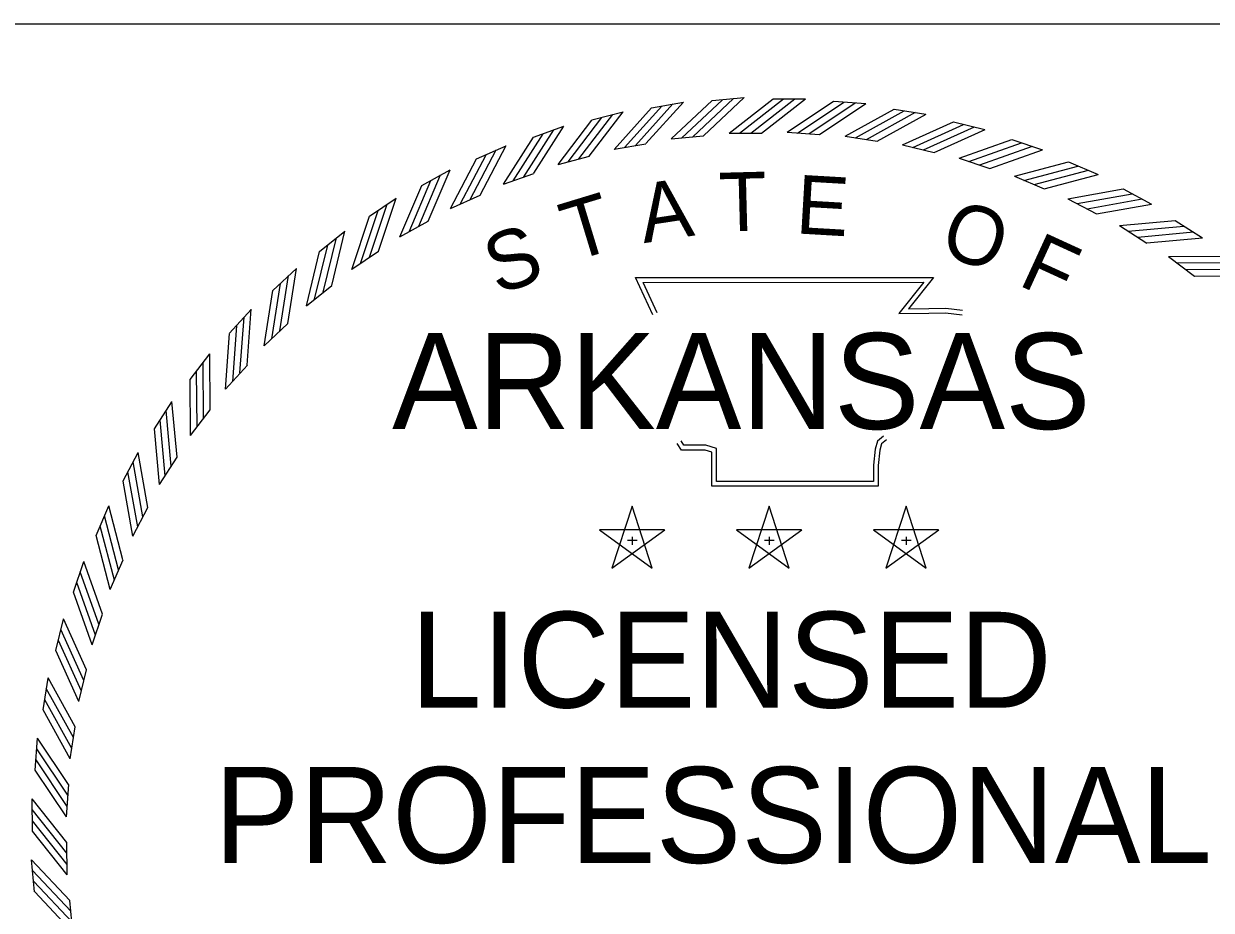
# Model space of a CAD drawing. Extents: x 0 to 1228740, y 0 to 152440.
# Drawn here: x 30.801 to 32.801, y 18.649 to 20.143 of the extents above; entities that cross this region are included whole.
import ezdxf

# ---------------------------------------------------------------- set-up
doc = ezdxf.new("R2010")
doc.units = 0
for name, color, linetype in [('R_Border', 7, 'Continuous'), ('STAMP_BOL', 7, 'Continuous'), ('STAMP_PP', 7, 'Continuous')]:
    doc.layers.add(name, color=color, linetype=linetype)

msp = doc.modelspace()

# ---------------------------------------------------------------- linework, layer by layer
at = {"layer": 'R_Border'}
msp.add_line((29.1131, 20.1432), (33.4231, 20.1432), dxfattribs=at)
at = {"layer": 'STAMP_BOL'}
for p, q in [((31.8584, 20.0015), (31.912, 20.0109)), ((31.9602, 20.0137), (32.0144, 20.0186)), ((32.0633, 20.0167), (32.1177, 20.0167)), ((32.1652, 20.0126), (32.2194, 20.0086)), ((31.7579, 19.981), (31.8105, 19.9948)), ((32.2669, 19.9994), (32.3206, 19.9909)), ((31.6595, 19.9522), (31.7108, 19.9703)), ((32.3671, 19.9778), (32.42, 19.965)), ((31.8916, 19.9492), (31.9459, 19.9542)), ((31.989, 19.9588), (32.0435, 19.9588)), ((32.0869, 19.9603), (32.1413, 19.9563)), ((32.1845, 19.9538), (32.2384, 19.9453)), ((32.4653, 19.9481), (32.5169, 19.9309)), ((31.5637, 19.9154), (31.6134, 19.9377)), ((31.7953, 19.9316), (31.849, 19.941)), ((32.2813, 19.9392), (32.3343, 19.9263)), ((31.7008, 19.9061), (31.7536, 19.9199)), ((32.3766, 19.9166), (32.4283, 19.8994)), ((32.5606, 19.9103), (32.6107, 19.8889)), ((31.4714, 19.8708), (31.519, 19.8972)), ((31.6088, 19.8729), (31.6602, 19.891)), ((32.4696, 19.8863), (32.5198, 19.8648)), ((32.6526, 19.8648), (32.7006, 19.8393)), ((31.383, 19.8188), (31.4283, 19.849)), ((31.5198, 19.8321), (31.5695, 19.8545)), ((32.5598, 19.8484), (32.608, 19.8229)), ((31.4344, 19.7842), (31.4821, 19.8106)), ((32.6466, 19.8031), (32.6926, 19.7737)), ((32.7404, 19.8119), (32.7862, 19.7825)), ((31.2992, 19.7596), (31.3419, 19.7934)), ((31.3533, 19.7294), (31.3987, 19.7597)), ((32.7294, 19.7509), (32.7727, 19.7178)), ((31.2206, 19.6937), (31.2603, 19.7309)), ((31.277, 19.6681), (31.3198, 19.702)), ((31.1477, 19.6216), (31.1842, 19.6619)), ((31.2061, 19.6007), (31.2459, 19.638)), ((31.0811, 19.5437), (31.1141, 19.5869)), ((31.1409, 19.5277), (31.1775, 19.5681)), ((31.021, 19.4605), (31.0504, 19.5063)), ((31.082, 19.4495), (31.1151, 19.4928)), ((30.9681, 19.3727), (30.9935, 19.4207)), ((31.0298, 19.3667), (31.0592, 19.4127)), ((30.9226, 19.2807), (30.944, 19.3308)), ((30.9845, 19.28), (31.01, 19.3281)), ((31.8255, 19.3302), (31.7915, 19.2258)), ((31.8594, 19.2258), (31.8256, 19.3303)), ((32.0563, 19.3302), (32.0222, 19.2258)), ((32.0902, 19.2258), (32.0564, 19.3303)), ((32.2871, 19.3302), (32.253, 19.2258)), ((32.321, 19.2258), (32.2871, 19.3303)), ((31.8804, 19.2904), (31.7705, 19.2905)), ((31.7706, 19.2904), (31.8594, 19.2257)), ((31.7916, 19.2258), (31.8805, 19.2903)), ((32.1112, 19.2904), (32.0013, 19.2905)), ((32.0014, 19.2904), (32.0902, 19.2257)), ((32.0224, 19.2258), (32.1113, 19.2903)), ((32.3419, 19.2904), (32.2321, 19.2905)), ((32.2322, 19.2904), (32.321, 19.2257)), ((32.2532, 19.2258), (32.3421, 19.2903)), ((31.8177, 19.2728), (31.834, 19.2728)), ((31.8256, 19.2787), (31.8256, 19.2649)), ((32.0485, 19.2728), (32.0648, 19.2728)), ((32.0564, 19.2787), (32.0564, 19.2649)), ((32.2793, 19.2728), (32.2956, 19.2728)), ((32.2872, 19.2787), (32.2872, 19.2649)), ((30.8848, 19.1854), (30.902, 19.237)), ((30.9466, 19.1897), (30.9681, 19.2399)), ((30.9163, 19.0967), (30.9335, 19.1484)), ((30.855, 19.0873), (30.8679, 19.1401)), ((30.8937, 19.0014), (30.9066, 19.0544)), ((30.8335, 18.987), (30.8419, 19.0407)), ((30.8791, 18.9046), (30.8876, 18.9585)), ((30.8203, 18.8853), (30.8243, 18.9395)), ((30.8726, 18.807), (30.8766, 18.8614)), ((30.8155, 18.7828), (30.815, 18.8372)), ((30.8741, 18.7091), (30.8736, 18.7637)), ((30.8192, 18.6803), (30.8142, 18.7345)), ((30.8837, 18.6117), (30.8787, 18.666))]:
    msp.add_line(p, q, dxfattribs=at)
for points in [[(31.8126, 19.9344), (31.8756, 20.0043)], [(31.8311, 19.9381), (31.8941, 20.008)], [(31.849, 19.9411), (31.912, 20.011)], [(31.8916, 19.9491), (31.9602, 20.0136)], [(31.909, 19.9506), (31.9776, 20.015)], [(31.9278, 19.9527), (31.9964, 20.0172)], [(31.9458, 19.9542), (32.0145, 20.0187)], [(31.9889, 19.9587), (32.0632, 20.0166)], [(32.0065, 19.9586), (32.0807, 20.0165)], [(32.0254, 19.959), (32.0996, 20.0169)], [(32.0435, 19.9588), (32.1177, 20.0167)], [(32.0868, 19.9603), (32.1651, 20.0126)], [(32.1043, 19.9588), (32.1825, 20.0111)], [(32.1231, 19.9579), (32.2014, 20.0101)], [(32.1412, 19.9564), (32.2195, 20.0087)], [(31.7178, 19.9103), (31.7748, 19.9852)], [(31.7359, 19.9155), (31.793, 19.9904)], [(31.7535, 19.92), (31.8106, 19.9948)], [(31.7953, 19.9315), (31.8583, 20.0014)], [(32.1845, 19.9537), (32.2668, 19.9994)], [(32.2017, 19.9508), (32.2841, 19.9965)], [(32.2205, 19.9483), (32.3028, 19.994)], [(32.2383, 19.9453), (32.3207, 19.991)], [(31.643, 19.8852), (31.6937, 19.9645)], [(31.6601, 19.8911), (31.7108, 19.9704)], [(31.7008, 19.906), (31.7579, 19.9809)], [(32.2812, 19.9391), (32.3671, 19.9778)], [(32.2982, 19.9348), (32.384, 19.9735)], [(32.3167, 19.9308), (32.4025, 19.9695)], [(32.3342, 19.9263), (32.4201, 19.965)], [(31.6087, 19.8728), (31.6594, 19.9521)], [(31.6253, 19.8785), (31.676, 19.9578)], [(32.3765, 19.9166), (32.4652, 19.9481)], [(31.5528, 19.8472), (31.5968, 19.9305)], [(31.5694, 19.8545), (31.6134, 19.9378)], [(32.393, 19.9109), (32.4818, 19.9424)], [(32.4111, 19.9053), (32.4998, 19.9368)], [(32.4282, 19.8994), (32.517, 19.9309)], [(31.5197, 19.8321), (31.5637, 19.9153)], [(31.5358, 19.8391), (31.5797, 19.9224)], [(32.4695, 19.8863), (32.5606, 19.9103)], [(32.4856, 19.8792), (32.5766, 19.9033)], [(31.4661, 19.802), (31.5031, 19.8886)], [(31.4821, 19.8106), (31.519, 19.8972)], [(32.5031, 19.8722), (32.5941, 19.8962)], [(32.5197, 19.8649), (32.6107, 19.8889)], [(31.4344, 19.7842), (31.4713, 19.8707)], [(31.4498, 19.7925), (31.4867, 19.8791)], [(32.5598, 19.8483), (32.6525, 19.8648)], [(31.3986, 19.7597), (31.4283, 19.849)], [(32.5752, 19.84), (32.6679, 19.8565)], [(32.5921, 19.8315), (32.6848, 19.848)], [(31.368, 19.7389), (31.3976, 19.8283)], [(31.3835, 19.7498), (31.4131, 19.8391)], [(32.608, 19.8229), (32.7007, 19.8394)], [(31.3533, 19.7293), (31.383, 19.8187)], [(32.6466, 19.8031), (32.7403, 19.8119)], [(31.3197, 19.702), (31.3419, 19.7935)], [(32.6612, 19.7935), (32.755, 19.8023)], [(32.6774, 19.7837), (32.7711, 19.7924)], [(31.2908, 19.6788), (31.313, 19.7703)], [(31.3054, 19.6909), (31.3276, 19.7823)], [(32.6925, 19.7738), (32.7863, 19.7825)], [(31.277, 19.668), (31.2992, 19.7595)], [(32.7293, 19.7509), (32.8235, 19.7518)], [(31.2458, 19.638), (31.2603, 19.731)], [(32.7431, 19.7401), (32.8373, 19.7411)], [(32.7584, 19.729), (32.8526, 19.7299)], [(31.2189, 19.6125), (31.2335, 19.7055)], [(31.2324, 19.6257), (31.247, 19.7187)], [(31.8606, 19.6525), (31.8316, 19.7154), (32.3333, 19.7156), (32.2914, 19.663), (32.3255, 19.6634), (32.354, 19.6638), (32.3824, 19.6607)], [(31.8678, 19.6559), (31.844, 19.7074), (32.3169, 19.7077), (32.2748, 19.6548), (32.3256, 19.6555), (32.3536, 19.6558), (32.3816, 19.6528)], [(32.7727, 19.7179), (32.8669, 19.7188)], [(31.2061, 19.6006), (31.2206, 19.6936)], [(31.1651, 19.5548), (31.172, 19.6487)], [(31.1774, 19.5681), (31.1842, 19.662)], [(31.1528, 19.5405), (31.1596, 19.6344)], [(31.1409, 19.5276), (31.1477, 19.6215)], [(31.115, 19.4928), (31.1141, 19.587)], [(31.1039, 19.4785), (31.1029, 19.5727)], [(31.082, 19.4494), (31.0811, 19.5436)], [(31.0928, 19.4632), (31.0918, 19.5574)], [(31.0591, 19.4126), (31.0504, 19.5064)], [(31.0492, 19.3975), (31.0405, 19.4912)], [(31.0393, 19.3813), (31.0306, 19.4751)], [(31.0298, 19.3667), (31.021, 19.4604)], [(32.2493, 19.4484), (32.2387, 19.4399), (32.235, 19.4264), (32.2321, 19.3993), (32.2321, 19.3721), (31.9679, 19.3721), (31.9679, 19.411), (31.9679, 19.4273), (31.9497, 19.4328), (31.913, 19.4328), (31.9083, 19.4401)], [(32.2543, 19.4423), (32.2457, 19.4353), (32.2429, 19.4249), (32.24, 19.3989), (32.24, 19.3642), (31.9599, 19.3642), (31.9599, 19.411), (31.9599, 19.4214), (31.9486, 19.4249), (31.9087, 19.4249), (31.9016, 19.4357)], [(31.0013, 19.3122), (30.9849, 19.4049)], [(31.01, 19.3281), (30.9935, 19.4208)], [(30.9929, 19.2953), (30.9764, 19.388)], [(30.9845, 19.2799), (30.9681, 19.3726)], [(30.968, 19.2398), (30.944, 19.3308)], [(30.9607, 19.2232), (30.9367, 19.3142)], [(30.9537, 19.2057), (30.9296, 19.2967)], [(30.9466, 19.1896), (30.9226, 19.2807)], [(30.9335, 19.1484), (30.902, 19.2371)], [(30.9276, 19.1312), (30.8961, 19.2199)], [(30.9163, 19.0966), (30.8848, 19.1853)], [(30.922, 19.1131), (30.8905, 19.2019)], [(30.9066, 19.0544), (30.8679, 19.1402)], [(30.8981, 19.0183), (30.8594, 19.1041)], [(30.9021, 19.0368), (30.8634, 19.1226)], [(30.8938, 19.0013), (30.8551, 19.0872)], [(30.8846, 18.9406), (30.8389, 19.0229)], [(30.8876, 18.9585), (30.8419, 19.0408)], [(30.8821, 18.9218), (30.8364, 19.0042)], [(30.8792, 18.9046), (30.8335, 18.9869)], [(30.8765, 18.8613), (30.8242, 18.9396)], [(30.875, 18.8432), (30.8227, 18.9215)], [(30.8726, 18.8069), (30.8203, 18.8852)], [(30.8741, 18.8244), (30.8218, 18.9026)], [(30.8736, 18.7636), (30.815, 18.8373)], [(30.8736, 18.7455), (30.815, 18.8192)], [(30.8741, 18.7266), (30.8156, 18.8003)], [(30.8741, 18.7091), (30.8156, 18.7828)], [(30.8787, 18.666), (30.8142, 18.7346)], [(30.8802, 18.6479), (30.8157, 18.7165)], [(30.8823, 18.6291), (30.8178, 18.6977)], [(30.8838, 18.6117), (30.8193, 18.6803)]]:
    msp.add_lwpolyline(points, dxfattribs=at)
at = {"layer": 'STAMP_PP'}
for p, q in [((31.8584, 20.0015), (31.912, 20.0109)), ((31.9602, 20.0137), (32.0144, 20.0186)), ((32.0633, 20.0167), (32.1177, 20.0167)), ((32.1652, 20.0126), (32.2194, 20.0086)), ((31.7579, 19.981), (31.8105, 19.9948)), ((32.2669, 19.9994), (32.3206, 19.9909)), ((31.6595, 19.9522), (31.7108, 19.9703)), ((32.3671, 19.9778), (32.42, 19.965)), ((31.8916, 19.9492), (31.9459, 19.9542)), ((31.989, 19.9588), (32.0435, 19.9588)), ((32.0869, 19.9603), (32.1413, 19.9563)), ((32.1845, 19.9538), (32.2384, 19.9453)), ((32.4653, 19.9481), (32.5169, 19.9309)), ((31.5637, 19.9154), (31.6134, 19.9377)), ((31.7953, 19.9316), (31.849, 19.941)), ((32.2813, 19.9392), (32.3343, 19.9263)), ((31.7008, 19.9061), (31.7536, 19.9199)), ((32.3766, 19.9166), (32.4283, 19.8994)), ((32.5606, 19.9103), (32.6107, 19.8889)), ((31.4714, 19.8708), (31.519, 19.8972)), ((31.6088, 19.8729), (31.6602, 19.891)), ((32.4696, 19.8863), (32.5198, 19.8648)), ((32.6526, 19.8648), (32.7006, 19.8393)), ((31.383, 19.8188), (31.4283, 19.849)), ((31.5198, 19.8321), (31.5695, 19.8545)), ((32.5598, 19.8484), (32.608, 19.8229)), ((31.4344, 19.7842), (31.4821, 19.8106)), ((32.6466, 19.8031), (32.6926, 19.7737)), ((32.7404, 19.8119), (32.7862, 19.7825)), ((31.2992, 19.7596), (31.3419, 19.7934)), ((31.3533, 19.7294), (31.3987, 19.7597)), ((32.7294, 19.7509), (32.7727, 19.7178)), ((31.2206, 19.6937), (31.2603, 19.7309)), ((31.277, 19.6681), (31.3198, 19.702)), ((31.1477, 19.6216), (31.1842, 19.6619)), ((31.2061, 19.6007), (31.2459, 19.638)), ((31.0811, 19.5437), (31.1141, 19.5869)), ((31.1409, 19.5277), (31.1775, 19.5681)), ((31.021, 19.4605), (31.0504, 19.5063)), ((31.082, 19.4495), (31.1151, 19.4928)), ((30.9681, 19.3727), (30.9935, 19.4207)), ((31.0298, 19.3667), (31.0592, 19.4127)), ((30.9226, 19.2807), (30.944, 19.3308)), ((30.9845, 19.28), (31.01, 19.3281)), ((31.8255, 19.3302), (31.7915, 19.2258)), ((31.8594, 19.2258), (31.8256, 19.3303)), ((32.0563, 19.3302), (32.0222, 19.2258)), ((32.0902, 19.2258), (32.0564, 19.3303)), ((32.2871, 19.3302), (32.253, 19.2258)), ((32.321, 19.2258), (32.2871, 19.3303)), ((31.8804, 19.2904), (31.7705, 19.2905)), ((31.7706, 19.2904), (31.8594, 19.2257)), ((31.7916, 19.2258), (31.8805, 19.2903)), ((32.1112, 19.2904), (32.0013, 19.2905)), ((32.0014, 19.2904), (32.0902, 19.2257)), ((32.0224, 19.2258), (32.1113, 19.2903)), ((32.3419, 19.2904), (32.2321, 19.2905)), ((32.2322, 19.2904), (32.321, 19.2257)), ((32.2532, 19.2258), (32.3421, 19.2903)), ((31.8177, 19.2728), (31.834, 19.2728)), ((31.8256, 19.2787), (31.8256, 19.2649)), ((32.0485, 19.2728), (32.0648, 19.2728)), ((32.0564, 19.2787), (32.0564, 19.2649)), ((32.2793, 19.2728), (32.2956, 19.2728)), ((32.2872, 19.2787), (32.2872, 19.2649)), ((30.8848, 19.1854), (30.902, 19.237)), ((30.9466, 19.1897), (30.9681, 19.2399)), ((30.9163, 19.0967), (30.9335, 19.1484)), ((30.855, 19.0873), (30.8679, 19.1401)), ((30.8937, 19.0014), (30.9066, 19.0544)), ((30.8335, 18.987), (30.8419, 19.0407)), ((30.8791, 18.9046), (30.8876, 18.9585)), ((30.8203, 18.8853), (30.8243, 18.9395)), ((30.8726, 18.807), (30.8766, 18.8614)), ((30.8155, 18.7828), (30.815, 18.8372)), ((30.8741, 18.7091), (30.8736, 18.7637)), ((30.8192, 18.6803), (30.8142, 18.7345)), ((30.8837, 18.6117), (30.8787, 18.666))]:
    msp.add_line(p, q, dxfattribs=at)
for points in [[(31.8126, 19.9344), (31.8756, 20.0043)], [(31.8311, 19.9381), (31.8941, 20.008)], [(31.849, 19.9411), (31.912, 20.011)], [(31.8916, 19.9491), (31.9602, 20.0136)], [(31.909, 19.9506), (31.9776, 20.015)], [(31.9278, 19.9527), (31.9964, 20.0172)], [(31.9458, 19.9542), (32.0145, 20.0187)], [(31.9889, 19.9587), (32.0632, 20.0166)], [(32.0065, 19.9586), (32.0807, 20.0165)], [(32.0254, 19.959), (32.0996, 20.0169)], [(32.0435, 19.9588), (32.1177, 20.0167)], [(32.0868, 19.9603), (32.1651, 20.0126)], [(32.1043, 19.9588), (32.1825, 20.0111)], [(32.1231, 19.9579), (32.2014, 20.0101)], [(32.1412, 19.9564), (32.2195, 20.0087)], [(31.7178, 19.9103), (31.7748, 19.9852)], [(31.7359, 19.9155), (31.793, 19.9904)], [(31.7535, 19.92), (31.8106, 19.9948)], [(31.7953, 19.9315), (31.8583, 20.0014)], [(32.1845, 19.9537), (32.2668, 19.9994)], [(32.2017, 19.9508), (32.2841, 19.9965)], [(32.2205, 19.9483), (32.3028, 19.994)], [(32.2383, 19.9453), (32.3207, 19.991)], [(31.643, 19.8852), (31.6937, 19.9645)], [(31.6601, 19.8911), (31.7108, 19.9704)], [(31.7008, 19.906), (31.7579, 19.9809)], [(32.2812, 19.9391), (32.3671, 19.9778)], [(32.2982, 19.9348), (32.384, 19.9735)], [(32.3167, 19.9308), (32.4025, 19.9695)], [(32.3342, 19.9263), (32.4201, 19.965)], [(31.6087, 19.8728), (31.6594, 19.9521)], [(31.6253, 19.8785), (31.676, 19.9578)], [(32.3765, 19.9166), (32.4652, 19.9481)], [(31.5528, 19.8472), (31.5968, 19.9305)], [(31.5694, 19.8545), (31.6134, 19.9378)], [(32.393, 19.9109), (32.4818, 19.9424)], [(32.4111, 19.9053), (32.4998, 19.9368)], [(32.4282, 19.8994), (32.517, 19.9309)], [(31.5197, 19.8321), (31.5637, 19.9153)], [(31.5358, 19.8391), (31.5797, 19.9224)], [(32.4695, 19.8863), (32.5606, 19.9103)], [(32.4856, 19.8792), (32.5766, 19.9033)], [(31.4661, 19.802), (31.5031, 19.8886)], [(31.4821, 19.8106), (31.519, 19.8972)], [(32.5031, 19.8722), (32.5941, 19.8962)], [(32.5197, 19.8649), (32.6107, 19.8889)], [(31.4344, 19.7842), (31.4713, 19.8707)], [(31.4498, 19.7925), (31.4867, 19.8791)], [(32.5598, 19.8483), (32.6525, 19.8648)], [(31.3986, 19.7597), (31.4283, 19.849)], [(32.5752, 19.84), (32.6679, 19.8565)], [(32.5921, 19.8315), (32.6848, 19.848)], [(31.368, 19.7389), (31.3976, 19.8283)], [(31.3835, 19.7498), (31.4131, 19.8391)], [(32.608, 19.8229), (32.7007, 19.8394)], [(31.3533, 19.7293), (31.383, 19.8187)], [(32.6466, 19.8031), (32.7403, 19.8119)], [(31.3197, 19.702), (31.3419, 19.7935)], [(32.6612, 19.7935), (32.755, 19.8023)], [(32.6774, 19.7837), (32.7711, 19.7924)], [(31.2908, 19.6788), (31.313, 19.7703)], [(31.3054, 19.6909), (31.3276, 19.7823)], [(32.6925, 19.7738), (32.7863, 19.7825)], [(31.277, 19.668), (31.2992, 19.7595)], [(32.7293, 19.7509), (32.8235, 19.7518)], [(31.2458, 19.638), (31.2603, 19.731)], [(32.7431, 19.7401), (32.8373, 19.7411)], [(32.7584, 19.729), (32.8526, 19.7299)], [(31.2189, 19.6125), (31.2335, 19.7055)], [(31.2324, 19.6257), (31.247, 19.7187)], [(31.8606, 19.6525), (31.8316, 19.7154), (32.3333, 19.7156), (32.2914, 19.663), (32.3255, 19.6634), (32.354, 19.6638), (32.3824, 19.6607)], [(31.8678, 19.6559), (31.844, 19.7074), (32.3169, 19.7077), (32.2748, 19.6548), (32.3256, 19.6555), (32.3536, 19.6558), (32.3816, 19.6528)], [(32.7727, 19.7179), (32.8669, 19.7188)], [(31.2061, 19.6006), (31.2206, 19.6936)], [(31.1651, 19.5548), (31.172, 19.6487)], [(31.1774, 19.5681), (31.1842, 19.662)], [(31.1528, 19.5405), (31.1596, 19.6344)], [(31.1409, 19.5276), (31.1477, 19.6215)], [(31.115, 19.4928), (31.1141, 19.587)], [(31.1039, 19.4785), (31.1029, 19.5727)], [(31.082, 19.4494), (31.0811, 19.5436)], [(31.0928, 19.4632), (31.0918, 19.5574)], [(31.0591, 19.4126), (31.0504, 19.5064)], [(31.0492, 19.3975), (31.0405, 19.4912)], [(31.0393, 19.3813), (31.0306, 19.4751)], [(31.0298, 19.3667), (31.021, 19.4604)], [(32.2493, 19.4484), (32.2387, 19.4399), (32.235, 19.4264), (32.2321, 19.3993), (32.2321, 19.3721), (31.9679, 19.3721), (31.9679, 19.411), (31.9679, 19.4273), (31.9497, 19.4328), (31.913, 19.4328), (31.9083, 19.4401)], [(32.2543, 19.4423), (32.2457, 19.4353), (32.2429, 19.4249), (32.24, 19.3989), (32.24, 19.3642), (31.9599, 19.3642), (31.9599, 19.411), (31.9599, 19.4214), (31.9486, 19.4249), (31.9087, 19.4249), (31.9016, 19.4357)], [(31.0013, 19.3122), (30.9849, 19.4049)], [(31.01, 19.3281), (30.9935, 19.4208)], [(30.9929, 19.2953), (30.9764, 19.388)], [(30.9845, 19.2799), (30.9681, 19.3726)], [(30.968, 19.2398), (30.944, 19.3308)], [(30.9607, 19.2232), (30.9367, 19.3142)], [(30.9537, 19.2057), (30.9296, 19.2967)], [(30.9466, 19.1896), (30.9226, 19.2807)], [(30.9335, 19.1484), (30.902, 19.2371)], [(30.9276, 19.1312), (30.8961, 19.2199)], [(30.9163, 19.0966), (30.8848, 19.1853)], [(30.922, 19.1131), (30.8905, 19.2019)], [(30.9066, 19.0544), (30.8679, 19.1402)], [(30.8981, 19.0183), (30.8594, 19.1041)], [(30.9021, 19.0368), (30.8634, 19.1226)], [(30.8938, 19.0013), (30.8551, 19.0872)], [(30.8846, 18.9406), (30.8389, 19.0229)], [(30.8876, 18.9585), (30.8419, 19.0408)], [(30.8821, 18.9218), (30.8364, 19.0042)], [(30.8792, 18.9046), (30.8335, 18.9869)], [(30.8765, 18.8613), (30.8242, 18.9396)], [(30.875, 18.8432), (30.8227, 18.9215)], [(30.8726, 18.8069), (30.8203, 18.8852)], [(30.8741, 18.8244), (30.8218, 18.9026)], [(30.8736, 18.7636), (30.815, 18.8373)], [(30.8736, 18.7455), (30.815, 18.8192)], [(30.8741, 18.7266), (30.8156, 18.8003)], [(30.8741, 18.7091), (30.8156, 18.7828)], [(30.8787, 18.666), (30.8142, 18.7346)], [(30.8802, 18.6479), (30.8157, 18.7165)], [(30.8823, 18.6291), (30.8178, 18.6977)], [(30.8838, 18.6117), (30.8193, 18.6803)]]:
    msp.add_lwpolyline(points, dxfattribs=at)

# ---------------------------------------------------------------- texts
at = {"layer": 'STAMP_BOL'}
for s, height, rotation, p in [('T', 0.099, 1.4789, (31.9731, 19.793)), ('E', 0.099, 356.672, (32.0998, 19.79)), ('A', 0.099, 8.6788, (31.8453, 19.7733)), ('T', 0.099, 16.9015, (31.7251, 19.742)), ('O', 0.099, 341.2218, (32.3401, 19.7561)), ('S', 0.099, 19.7726, (31.5992, 19.6855)), ('F', 0.099, 335.3628, (32.4735, 19.7039)), ('ARKANSAS', 0.16155, 360, (31.4214, 19.4603)), ('LICENSED', 0.16155, 360, (31.4521, 18.9908)), ('PROFESSIONAL', 0.161547, 360, (31.1214, 18.7292))]:
    msp.add_text(s, height=height, rotation=rotation, dxfattribs=at).set_placement(p)
at = {"layer": 'STAMP_PP'}
for s, rotation, p in [('T', 1.4789, (31.9731, 19.793)), ('E', 356.672, (32.0998, 19.79)), ('A', 8.6788, (31.8453, 19.7733)), ('T', 16.9015, (31.7251, 19.742)), ('O', 341.2218, (32.3401, 19.7561)), ('S', 19.7726, (31.5992, 19.6855)), ('F', 335.3628, (32.4735, 19.7039))]:
    msp.add_text(s, height=0.099, rotation=rotation, dxfattribs=at).set_placement(p)
for s, height, p in [('ARKANSAS', 0.16155, (31.4214, 19.4603)), ('LICENSED', 0.16155, (31.4521, 18.9908)), ('PROFESSIONAL', 0.161547, (31.1214, 18.7292))]:
    msp.add_text(s, height=height, dxfattribs=at).set_placement(p)

doc.saveas('drawing.dxf')
